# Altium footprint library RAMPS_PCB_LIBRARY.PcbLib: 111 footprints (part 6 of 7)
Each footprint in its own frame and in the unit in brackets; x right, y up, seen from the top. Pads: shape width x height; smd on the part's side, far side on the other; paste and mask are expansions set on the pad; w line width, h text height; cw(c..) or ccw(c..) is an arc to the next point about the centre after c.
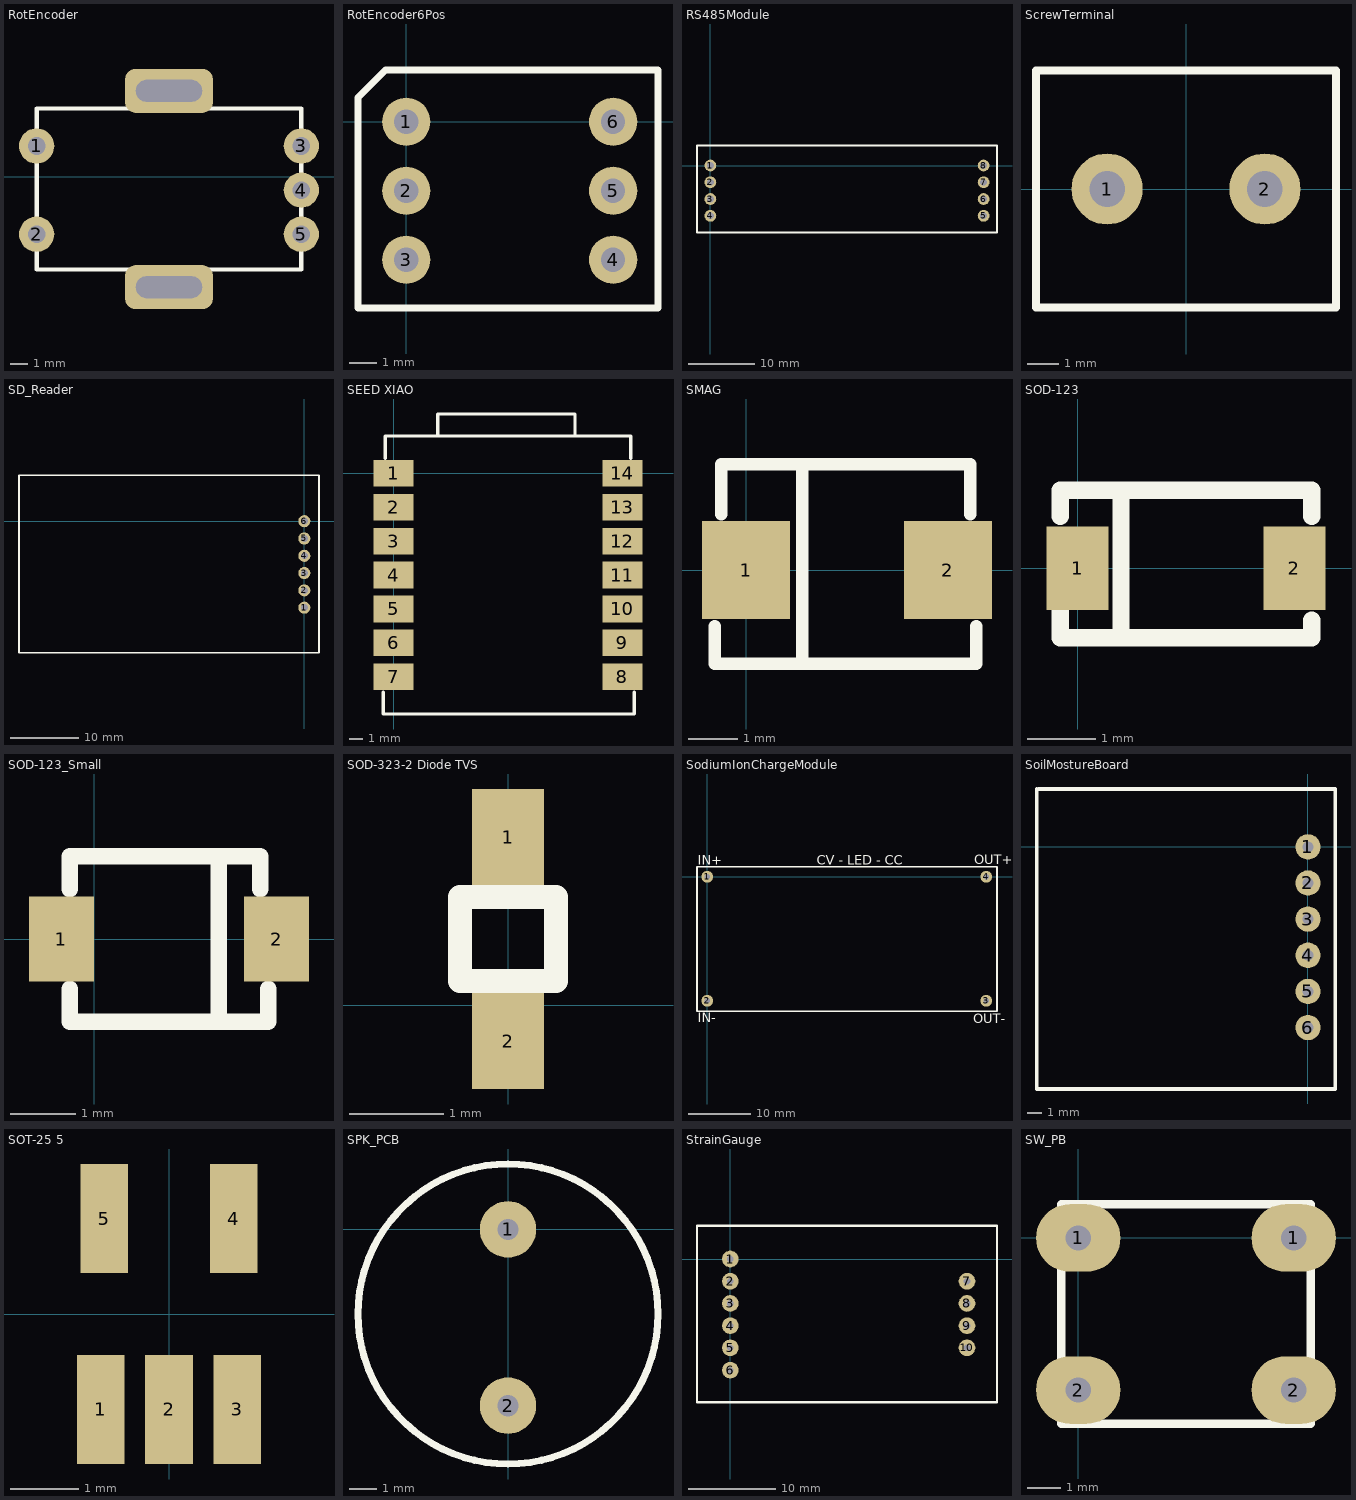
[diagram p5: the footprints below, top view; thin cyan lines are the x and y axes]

## RotEncoder [mil]
pads (7):
  round 80 hole 40: 1(1090,70) 2(1090,-130) 3(1690,70) 4(1690,-30) 5(1690,-130)
  rrect50% 200x100 hole 50 slot 150 at 0 deg: ""(1390,-250) ""(1390,195)
Top Overlay:
  lines w10: 1090,-210 1090,155 1115,155 1690,155 1690,-210 1090,-210

## RotEncoder6Pos [mil]
pads (6):
  round 70 hole 35: 1(0,0) 2(0,-100) 3(0,-200) 4(300,-200) 5(300,-100) 6(300,0)
Top Overlay:
  lines w10: -70,-270 -70,35 -30,75 365,75 365,-270 -70,-270

## RS485Module [mil]
pads (8):
  round 70 hole 40: 1(0,0) 2(0,-100) 3(0,-200) 4(0,-300) 5(1630,-300) 6(1630,-200) 7(1630,-100) 8(1630,0)
Top Overlay:
  lines w10: -80,-400 1710,-400 1710,120 -80,120 -80,-370 -80,-400

## ScrewTerminal [mil]
pads (2):
  round 90 hole 45: 1(-100,0) 2(100,0)
Top Overlay:
  lines w10: -190,-150 -190,150 190,150 190,-150 -190,-150

## SD_Reader [mil]
pads (6):
  round 70 hole 40: 1(0,-500) 2(0,-400) 3(0,-300) 4(0,-200) 5(0,-100) 6(0,0)
Top Overlay:
  lines w10: -1650,-760 85,-760 85,265 -1650,265 -1650,-760

## SEED XIAO [mm]
pads (14):
  rect 3x2 smd: 1(0,0) 2(0,-2.54) 3(0,-5.08) 4(0,-7.62) 5(0,-10.16) 6(0,-12.7) 7(0,-15.24) 8(17.145,-15.24) 9(17.145,-12.7) 10(17.145,-10.16) 11(17.145,-7.62) 12(17.145,-5.08) 13(17.145,-2.54) 14(17.145,0)
Top Overlay:
  lines w0.254: -0.762,-16.383 -0.762,-18.034 18.034,-18.034 18.034,-16.383 ; -0.635,1.143 -0.635,2.794 17.78,2.794 17.78,1.143 ; 3.302,2.921 3.302,4.445 13.589,4.445 13.589,2.921

## SMAG [mm]
pads (2):
  rect 1.8x2 smd: 1(0,0) 2(4.12,0)
Top Overlay:
  lines w0.254: -0.635,-1.143 -0.635,-1.905 4.699,-1.905 4.699,-1.143 ; -0.508,1.143 -0.508,2.159 4.572,2.159 4.572,1.143 ; 1.143,-1.778 1.143,2.032

## SOD-123 [mm]
pads (2):
  rect 0.91x1.22 smd: 1(0,0) 2(3.175,0)
Top Overlay:
  lines w0.254: -0.254,-0.635 -0.254,-1.016 3.429,-1.016 3.429,-0.762 ; -0.254,0.762 -0.254,1.143 3.429,1.143 3.429,0.762 ; 0.635,-0.889 0.635,1.016

## SOD-123_Small [mm]
pads (2):
  rect 1x1.3 smd: 1(-0.508,0) 2(2.794,0)
Top Overlay:
  lines w0.254: -0.381,-0.762 -0.381,-1.27 2.667,-1.27 2.667,-0.762 ; -0.381,0.762 -0.381,1.27 2.54,1.27 2.54,0.762 ; 1.905,-1.143 1.905,1.143

## SOD-323-2 Diode TVS [mil]
pads (2):
  rect 30x40 smd: 1(0,70) 2(0,-15)
Top Overlay:
  lines w10: -20,10 20,10 20,45 -20,45 -20,10

## SodiumIonChargeModule [mil]
pads (4):
  round 75 hole 35: 1(0,0) 2(0,-787.4) 3(1771.65,-787.4) 4(1771.65,0)
Top Overlay:
  lines w10: -65,-855 1840,-855 1840,65 -65,65 -65,-855
  text "CV - LED - CC" at 695,75 h60
  text "IN-" at -60,-925 h60
  text "IN+" at -60,75 h60
  text "OUT+" at 1695,80 h60
  text "OUT-" at 1690,-930 h60

## SoilMostureBoard [mil]
pads (6):
  round 70 hole 30: 1(0,0) 2(0,-100) 3(0,-200) 4(0,-300) 5(0,-400) 6(0,-500)
Top Overlay:
  lines w10: -750,-670 75,-670 ; -750,-665 -750,160 ; -745,160 75,160 75,-665

## SOT-25 5 [mm]
pads (5):
  rect 0.7x1.6 smd: 1(-1,-1.4) 2(0,-1.4) 3(1,-1.4) 4(0.95,1.4) 5(-0.95,1.4)

## SPK_PCB [mil]
pads (2):
  round 80 hole 30: 1(0,0) 2(0,-250)
Top Overlay:
  circle w10: c0,-120 r212.6

## StrainGauge [mil]
pads (10):
  round 75 hole 30: 1(0,0) 2(0,-100) 3(0,-200) 4(0,-300) 5(0,-400) 6(0,-500) 7(1065,-100) 8(1065,-200) 9(1065,-300) 10(1065,-400)
Top Overlay:
  lines w10: 1200,120 1200,150 -150,150 -150,-645 1200,-645 1200,125

## SW_PB [mil]
pads (4):
  oval 100x80 hole 30: 1(0,0) 1(255,0) 2(0,-180) 2(255,-180)
Top Overlay:
  lines w10: -20,-220 275,-220 275,40 -20,40 -20,-220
